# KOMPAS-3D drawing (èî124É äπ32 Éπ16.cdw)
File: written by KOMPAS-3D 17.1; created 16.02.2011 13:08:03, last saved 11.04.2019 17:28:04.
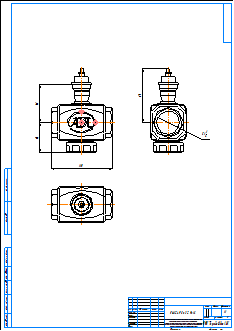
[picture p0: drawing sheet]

Title block, sheet 1: name: КМ124Р Ду32 Ру16; material: Внимание! Данный продукт является объектом авторского права ООО «Торговый Дом АДЛ». / Запрещается изменение, копирование, распространение / (в том числе путем копирования на другие сайты и ресурсы в Интернете) / или любое иное использование информации и объектов без предварительного / согласия правообладателя (ООО «Торговый Дом АДЛ»).; scale: 1:1; sheets: 1; organisation: ООО "Торговый дом АДЛ"; sheet format: A2; stored path: \\adlc.lan\data\АДЛ_ПКД\3D-модели\ADL production\Клапаны ГРАНРЕГ\Двухходовой клапан KM124P\KOMPAS 2D\КМ124Р Ду32 Ру16.cdw

Views: Спереди 1, Проекционный вид 2, Проекционный вид 3
Dimensions and other numbers on the sheet: 110; 54; 68; 97; 1:1; 1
